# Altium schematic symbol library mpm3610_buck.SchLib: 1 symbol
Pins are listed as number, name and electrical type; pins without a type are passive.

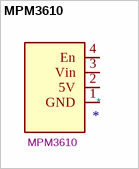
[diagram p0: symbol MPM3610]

## MPM3610
designator *  Reference: MPM3610
pins: 1 GND, 2 5V, 3 Vin, 4 En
